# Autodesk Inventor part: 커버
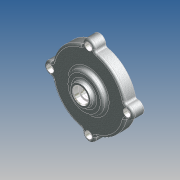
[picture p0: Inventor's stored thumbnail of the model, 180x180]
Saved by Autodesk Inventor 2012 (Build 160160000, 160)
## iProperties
Company: 한국ATC센터
Created: 2014-07
Part Number: 커버
Document SubType Name: 모델링
Designer: KYOUNG IL JANG
Material: 기본값
변환 표준: STEP AP214IS
파일 이름: C:\Users\SeoGD\Desktop\?쒗뿕\而ㅻ쾭-1.stp
전처리기: Build: 253, Release: 2010 SP1 - Date: Wed 07/29/2009
전송 단위: 밀리미터
불확실성: 0.01
Author: KYOUNG IL JANG
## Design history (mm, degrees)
sketch "스케치1"
  geometry: L1 (0, 0)-(0, 26); L2 (50, 0)-(50, 15); L3 (50, 15)-(25, 15); L4 (25, 15)-(25, 21); L5 (25, 21)-(15, 21); L6 (15, 21)-(13.66, 26); L7 (13.66, 26)-(10, 26); L8 (50, 0)-(45, 0); L9 (45, 0)-(45, 10); L10 (45, 10)-(14.5, 10); L11 (14.5, 10)-(13.266, 3); L12 (13.266, 3)-(11, 3); L13 (11, 3)-(11, 16); L14 (11, 16)-(7.5, 16); L15 (7.5, 16)-(7.5, 19); L16 (7.5, 19)-(10, 19); L17 (10, 19)-(10, 26)
  constraints: 34 end point, 10 parallel, 2 perpendicular, 2 point on line, 1 vertical
  dimensions: "d11" = 100 diameter of L2 L1; "d12" = 22 diameter of L13 L1; "d13" = 90 diameter of L9 L1; "d14" = 15 distance between parallel lines of L3 L8; "d15" = 10 distance between parallel lines of L8 L10; "d16" = 29 diameter of L10.end L1; "d17" = 100 deg angle of L11 L10; "d18" = 7 distance between parallel lines of L12 L10; "d19" = 13 distance between parallel lines of L14 L12; "d20" = 3 distance between parallel lines of L16 L14; "d21" = 15 diameter of L15 L1; "d22" = 20 diameter of L17 L1; "d23" = 30 diameter of L5.end L1; "d24" = 6 distance between parallel lines of L5 L3; "d25" = 50 diameter of L4 L1; "d26" = 105 deg angle of L5 L6; "d50" = 26 distance of L1.start L1.end
revolve "회전1" sketch "스케치1" stored, may be unused: angle "d27" = 90 deg
sketch "스케치2" dims "d29" = 104
  geometry: A1 r 8.5 centre (0, 52) between (8.074, 49.344) and (-8.074, 49.344); A2 r 50 centre (0, 0) between (-8.074, 49.344) and (8.074, 49.344) reference; 2 further points
  constraints: 4 point on circle, 2 vertical alignment, 1 centre point, 1 coincident, 2 other
  dimensions: "d28" = 17 diameter of A1
extrude "돌출1" join sketch "스케치2" stored distance "d30" = 10; taper "d31" = 0 deg
fillet "모깎기3" dims "d32" = 3
fillet "모깎기4" dims "d45" = 3, "d46" = 0.2
chamfer "모따기1" distance "d47" = 1; stored, may be unused: second distance "d48" = 2, angle "d49" = 45 deg
hole "구멍2" diameter "d38" = 5.5; stored, may be unused: countersink angle "d42" = 90 deg, drill point angle "d44" = 118 deg; dims "d36" = 10, "d37" = 10, "d39" = 6, "d40" = 9.5, "d41" = 5.4, "d43" = 8
node "솔리드1"
node "솔리드 본체"
node "곡면 본체"
pattern_circular "원형 패턴1" dims angle "d34" = 360 deg
pattern_circular "원형 패턴2" dims angle "d52" = 360 deg
node "솔리드2"
